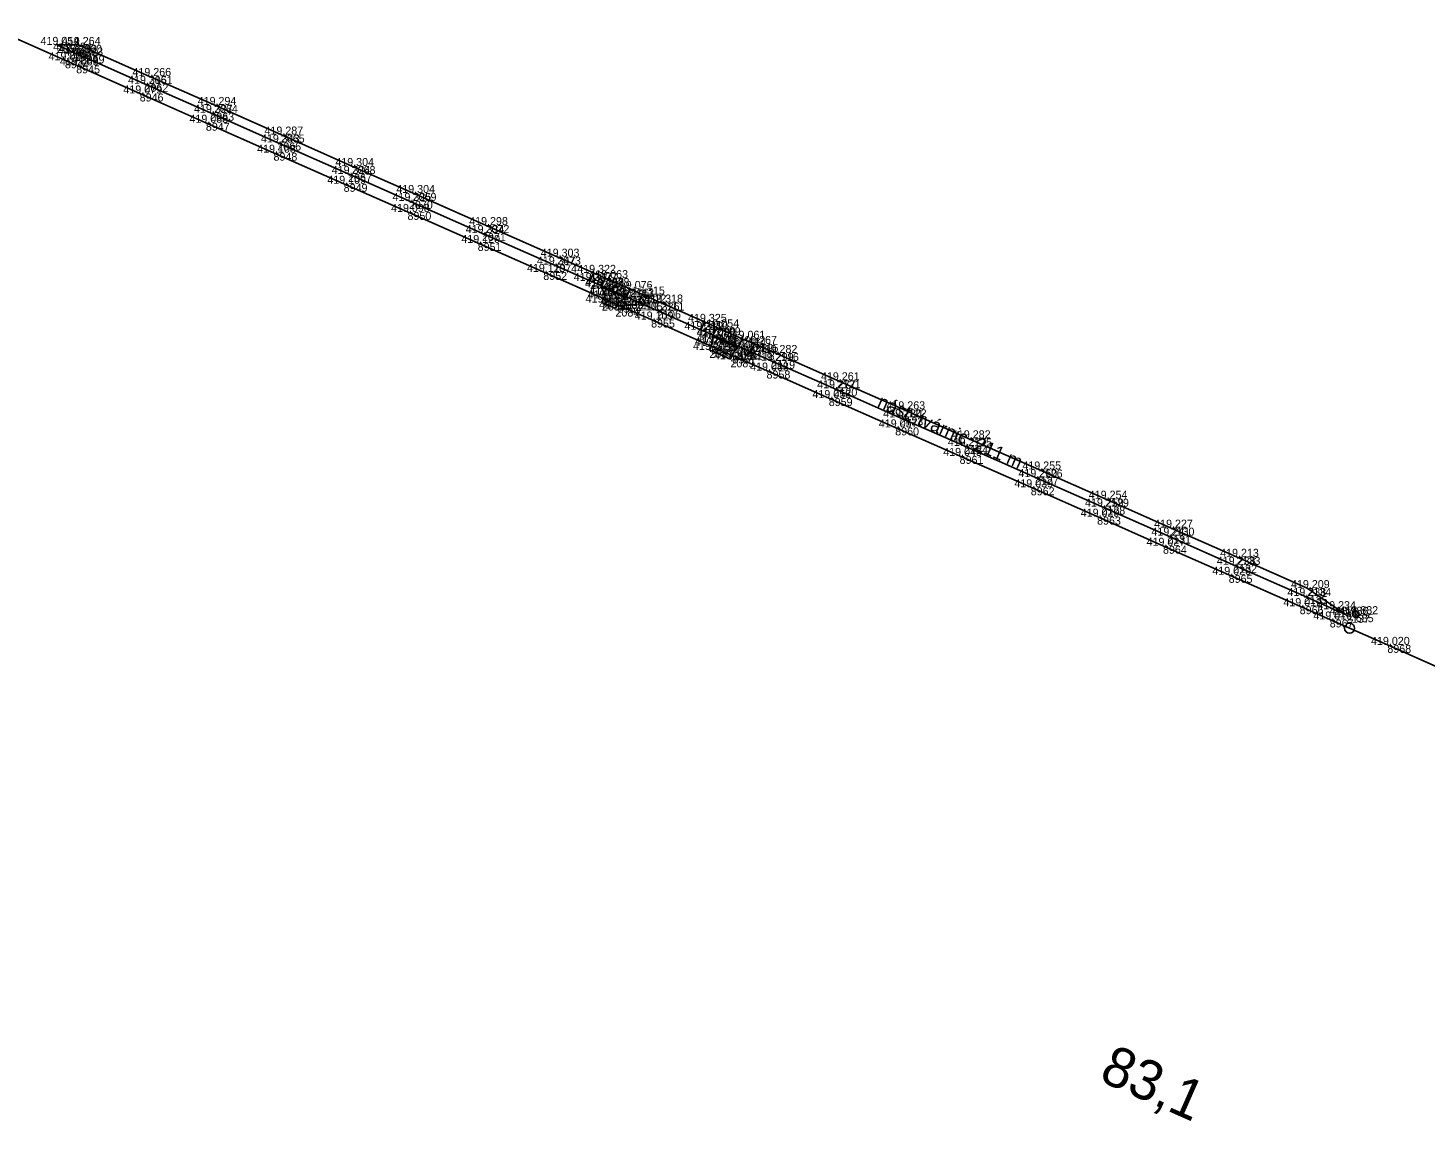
# Model space of a CAD drawing. Extents: x -599511 to -595511, y -1067427 to -1062061.
# Drawn here: x -598996.7 to -598787.3, y -1062489.7 to -1062325.8 of the extents above; entities that cross this region are included whole.
import ezdxf

# ---------------------------------------------------------------- set-up
doc = ezdxf.new("R2010")
doc.units = 0
for name, color, linetype in [('Vrstva 1', 7, 'Continuous'), ('Vrstva 14', 7, 'Continuous'), ('Vrstva 4', 7, 'Continuous'), ('Vrstva 60', 7, 'Continuous'), ('Vrstva 61', 7, 'Continuous'), ('Vrstva 7', 7, 'Continuous')]:
    doc.layers.add(name, color=color, linetype=linetype)

msp = doc.modelspace()

# ---------------------------------------------------------------- linework, layer by layer
at = {"layer": 'Vrstva 1'}
msp.add_lwpolyline([(-599002.16, -1062325.8), (-598991.2, -1062330.65), (-598989.51, -1062331.4), (-598979.99, -1062335.62), (-598970.07, -1062340.01), (-598959.93, -1062344.5), (-598949.41, -1062349.16), (-598939.84, -1062353.38), (-598929.32, -1062358.03), (-598919.48, -1062362.38), (-598910.47, -1062366.35), (-598908.33, -1062367.29), (-598903.32, -1062369.51), (-598894.33, -1062373.48), (-598891.15, -1062374.89), (-598886.01, -1062377.16), (-598876.68, -1062381.28), (-598866.72, -1062385.68), (-598857.06, -1062389.95), (-598846.4, -1062394.66), (-598836.45, -1062399.06), (-598826.57, -1062403.42), (-598816.72, -1062407.78), (-598806.07, -1062412.48), (-598801.57, -1062414.47), (-598792.93, -1062418.28), (-598782.71, -1062422.8)], dxfattribs=at)
at = {"layer": 'Vrstva 14'}
for p, q in [((-598912.46, -1062363.71), (-598911.94, -1062362.51)), ((-598910.72, -1062364.45), (-598910.13, -1062363.31)), ((-598907, -1062366.09), (-598906.45, -1062364.93)), ((-598905.14, -1062366.95), (-598904.6, -1062365.76)), ((-598895.86, -1062371.05), (-598895.33, -1062369.86)), ((-598893.99, -1062371.86), (-598893.46, -1062370.68)), ((-598890.2, -1062373.54), (-598889.64, -1062372.39)), ((-598888.36, -1062374.35), (-598887.8, -1062373.17))]:
    msp.add_line(p, q, dxfattribs=at)
msp.add_lwpolyline([(-598799.13, -1062413.77), (-598800.99, -1062412.93), (-598805.46, -1062410.95), (-598816.05, -1062406.27), (-598825.94, -1062401.89), (-598835.8, -1062397.54), (-598845.79, -1062393.13), (-598856.38, -1062388.46), (-598866.08, -1062384.18), (-598875.97, -1062379.82), (-598885.3, -1062375.7), (-598888.36, -1062374.35), (-598890.2, -1062373.54), (-598893.99, -1062371.86), (-598895.86, -1062371.05), (-598902.41, -1062368.15), (-598905.14, -1062366.95), (-598907, -1062366.09), (-598910.72, -1062364.45), (-598912.46, -1062363.71), (-598917.99, -1062361.27), (-598928.67, -1062356.55), (-598939.62, -1062351.72), (-598948.75, -1062347.68), (-598959.36, -1062342.97), (-598969.4, -1062338.51), (-598979.27, -1062334.17), (-598988.84, -1062329.93), (-598989.76, -1062329.53), (-598990.51, -1062329.2), (-598992.41, -1062328.34), (-598989.21, -1062328.35), (-598978.63, -1062333.01), (-598968.85, -1062337.34), (-598958.83, -1062341.78), (-598948.21, -1062346.5), (-598939.07, -1062350.54), (-598928.14, -1062355.35), (-598917.41, -1062360.09), (-598911.94, -1062362.51), (-598910.13, -1062363.31), (-598906.45, -1062364.93), (-598904.6, -1062365.76), (-598901.89, -1062366.96), (-598895.33, -1062369.86), (-598893.46, -1062370.68), (-598889.64, -1062372.39), (-598887.8, -1062373.17), (-598884.74, -1062374.52), (-598875.49, -1062378.62), (-598865.58, -1062382.97), (-598855.78, -1062387.32), (-598845.19, -1062391.99), (-598835.25, -1062396.37), (-598825.43, -1062400.71), (-598815.54, -1062405.08), (-598804.93, -1062409.77)], close=True, dxfattribs=at)
at = {"layer": 'Vrstva 4'}
for points in [[(-598910.78, -1062364.68), (-598910.2, -1062365.77), (-598910.69, -1062366.96), (-598908.66, -1062367.86), (-598908.05, -1062366.74), (-598907.11, -1062366.28)], [(-598894.04, -1062372.07), (-598890.35, -1062373.71), (-598890.88, -1062374.33), (-598891.42, -1062375.47), (-598894.58, -1062374.06), (-598894.06, -1062372.91)]]:
    msp.add_lwpolyline(points, close=True, dxfattribs=at)
at = {"layer": 'Vrstva 60'}
for p, q in [((-598992.41, -1062328.34), (-598992.41, -1062328.34)), ((-598990.51, -1062329.2), (-598990.51, -1062329.2)), ((-598989.76, -1062329.53), (-598989.76, -1062329.53)), ((-598989.21, -1062328.35), (-598989.21, -1062328.35)), ((-598988.84, -1062329.93), (-598988.84, -1062329.93)), ((-598991.2, -1062330.65), (-598991.2, -1062330.65)), ((-598989.51, -1062331.4), (-598989.51, -1062331.4)), ((-598979.27, -1062334.17), (-598979.27, -1062334.17)), ((-598978.63, -1062333.01), (-598978.63, -1062333.01)), ((-598979.99, -1062335.62), (-598979.99, -1062335.62)), ((-598968.85, -1062337.34), (-598968.85, -1062337.34)), ((-598970.07, -1062340.01), (-598970.07, -1062340.01)), ((-598969.4, -1062338.51), (-598969.4, -1062338.51)), ((-598958.83, -1062341.78), (-598958.83, -1062341.78)), ((-598959.93, -1062344.5), (-598959.93, -1062344.5)), ((-598959.36, -1062342.97), (-598959.36, -1062342.97)), ((-598948.21, -1062346.5), (-598948.21, -1062346.5)), ((-598948.75, -1062347.68), (-598948.75, -1062347.68)), ((-598949.41, -1062349.16), (-598949.41, -1062349.16)), ((-598939.07, -1062350.54), (-598939.07, -1062350.54)), ((-598939.62, -1062351.72), (-598939.62, -1062351.72)), ((-598939.84, -1062353.38), (-598939.84, -1062353.38)), ((-598928.67, -1062356.55), (-598928.67, -1062356.55)), ((-598928.14, -1062355.35), (-598928.14, -1062355.35)), ((-598929.32, -1062358.03), (-598929.32, -1062358.03)), ((-598917.99, -1062361.27), (-598917.99, -1062361.27)), ((-598917.41, -1062360.09), (-598917.41, -1062360.09)), ((-598919.48, -1062362.38), (-598919.48, -1062362.38)), ((-598911.94, -1062362.51), (-598911.94, -1062362.51)), ((-598910.13, -1062363.31), (-598910.13, -1062363.31)), ((-598912.46, -1062363.71), (-598912.46, -1062363.71)), ((-598910.78, -1062364.68), (-598910.78, -1062364.68)), ((-598910.72, -1062364.45), (-598910.72, -1062364.45)), ((-598906.45, -1062364.93), (-598906.45, -1062364.93)), ((-598910.69, -1062366.96), (-598910.69, -1062366.96)), ((-598910.47, -1062366.35), (-598910.47, -1062366.35)), ((-598910.2, -1062365.77), (-598910.2, -1062365.77)), ((-598908.33, -1062367.29), (-598908.33, -1062367.29)), ((-598908.05, -1062366.74), (-598908.05, -1062366.74)), ((-598907.11, -1062366.28), (-598907.11, -1062366.28)), ((-598907, -1062366.09), (-598907, -1062366.09)), ((-598905.14, -1062366.95), (-598905.14, -1062366.95)), ((-598904.6, -1062365.76), (-598904.6, -1062365.76)), ((-598901.89, -1062366.96), (-598901.89, -1062366.96)), ((-598908.66, -1062367.86), (-598908.66, -1062367.86)), ((-598903.32, -1062369.51), (-598903.32, -1062369.51)), ((-598902.41, -1062368.15), (-598902.41, -1062368.15)), ((-598895.86, -1062371.05), (-598895.86, -1062371.05)), ((-598895.33, -1062369.86), (-598895.33, -1062369.86)), ((-598893.99, -1062371.86), (-598893.99, -1062371.86)), ((-598893.46, -1062370.68), (-598893.46, -1062370.68)), ((-598894.33, -1062373.48), (-598894.33, -1062373.48)), ((-598894.06, -1062372.91), (-598894.06, -1062372.91)), ((-598894.04, -1062372.07), (-598894.04, -1062372.07)), ((-598890.35, -1062373.71), (-598890.35, -1062373.71)), ((-598890.2, -1062373.54), (-598890.2, -1062373.54)), ((-598889.64, -1062372.39), (-598889.64, -1062372.39)), ((-598887.8, -1062373.17), (-598887.8, -1062373.17)), ((-598894.58, -1062374.06), (-598894.58, -1062374.06)), ((-598891.42, -1062375.47), (-598891.42, -1062375.47)), ((-598891.15, -1062374.89), (-598891.15, -1062374.89)), ((-598890.88, -1062374.33), (-598890.88, -1062374.33)), ((-598888.36, -1062374.35), (-598888.36, -1062374.35)), ((-598885.3, -1062375.7), (-598885.3, -1062375.7)), ((-598884.74, -1062374.52), (-598884.74, -1062374.52)), ((-598886.01, -1062377.16), (-598886.01, -1062377.16)), ((-598875.97, -1062379.82), (-598875.97, -1062379.82)), ((-598875.49, -1062378.62), (-598875.49, -1062378.62)), ((-598876.68, -1062381.28), (-598876.68, -1062381.28)), ((-598866.08, -1062384.18), (-598866.08, -1062384.18)), ((-598865.58, -1062382.97), (-598865.58, -1062382.97)), ((-598866.72, -1062385.68), (-598866.72, -1062385.68)), ((-598856.38, -1062388.46), (-598856.38, -1062388.46)), ((-598855.78, -1062387.32), (-598855.78, -1062387.32)), ((-598857.06, -1062389.95), (-598857.06, -1062389.95)), ((-598845.19, -1062391.99), (-598845.19, -1062391.99)), ((-598846.4, -1062394.66), (-598846.4, -1062394.66)), ((-598845.79, -1062393.13), (-598845.79, -1062393.13)), ((-598835.25, -1062396.37), (-598835.25, -1062396.37)), ((-598836.45, -1062399.06), (-598836.45, -1062399.06)), ((-598835.8, -1062397.54), (-598835.8, -1062397.54)), ((-598825.43, -1062400.71), (-598825.43, -1062400.71)), ((-598825.94, -1062401.89), (-598825.94, -1062401.89)), ((-598826.57, -1062403.42), (-598826.57, -1062403.42)), ((-598815.54, -1062405.08), (-598815.54, -1062405.08)), ((-598816.05, -1062406.27), (-598816.05, -1062406.27)), ((-598816.72, -1062407.78), (-598816.72, -1062407.78)), ((-598805.46, -1062410.95), (-598805.46, -1062410.95)), ((-598804.93, -1062409.77), (-598804.93, -1062409.77)), ((-598806.07, -1062412.48), (-598806.07, -1062412.48)), ((-598800.99, -1062412.93), (-598800.99, -1062412.93)), ((-598799.13, -1062413.77), (-598799.13, -1062413.77)), ((-598797.66, -1062413.68), (-598797.66, -1062413.68)), ((-598801.57, -1062414.47), (-598801.57, -1062414.47)), ((-598792.93, -1062418.28), (-598792.93, -1062418.28))]:
    msp.add_line(p, q, dxfattribs=at)
at = {"layer": 'Vrstva 7'}
msp.add_line((-598797.71, -1062413.65), (-598797.62, -1062413.7), dxfattribs=at)
for centre, radius in [((-598797.66, -1062413.68), 0.5), ((-598798.59, -1062415.79), 0.75)]:
    msp.add_circle(centre, radius, dxfattribs=at)

# ---------------------------------------------------------------- texts
at = {"layer": 'Vrstva 14'}
msp.add_text('nást. tvárnic. 211 m', height=2, rotation=336.2761, dxfattribs=at).set_placement((-598869.53, -1062382.52))
at = {"layer": 'Vrstva 60'}
for s, p in [('2056', (-598992.41, -1062329.54)), ('2057', (-598990.51, -1062330.4)), ('2058', (-598989.76, -1062330.73)), ('2060', (-598989.21, -1062329.55)), ('2059', (-598988.84, -1062331.13)), ('8944', (-598991.2, -1062331.85)), ('8945', (-598989.51, -1062332.6)), ('2062', (-598979.27, -1062335.37)), ('2061', (-598978.63, -1062334.21)), ('8946', (-598979.99, -1062336.82)), ('2064', (-598968.85, -1062338.54)), ('8947', (-598970.07, -1062341.21)), ('2063', (-598969.4, -1062339.71)), ('2065', (-598958.83, -1062342.98)), ('8948', (-598959.93, -1062345.7)), ('2066', (-598959.36, -1062344.17)), ('2068', (-598948.21, -1062347.7)), ('2067', (-598948.75, -1062348.88)), ('8949', (-598949.41, -1062350.36)), ('2069', (-598939.07, -1062351.74)), ('2070', (-598939.62, -1062352.92)), ('8950', (-598939.84, -1062354.58)), ('2071', (-598928.67, -1062357.75)), ('2072', (-598928.14, -1062356.55)), ('8951', (-598929.32, -1062359.23)), ('2074', (-598917.99, -1062362.47)), ('2073', (-598917.41, -1062361.29)), ('8952', (-598919.48, -1062363.58)), ('2077', (-598911.94, -1062363.71)), ('2078', (-598910.13, -1062364.51)), ('2075', (-598912.46, -1062364.91)), ('2079', (-598910.78, -1062365.88)), ('2076', (-598910.72, -1062365.65)), ('2113', (-598906.45, -1062366.13)), ('2083', (-598910.69, -1062368.16)), ('8953', (-598910.47, -1062367.55)), ('2086', (-598910.2, -1062366.97)), ('8954', (-598908.33, -1062368.49)), ('2085', (-598908.05, -1062367.94)), ('2080', (-598907.11, -1062367.48)), ('2103', (-598907, -1062367.29)), ('2105', (-598905.14, -1062368.15)), ('2112', (-598904.6, -1062366.96)), ('2111', (-598901.89, -1062368.16)), ('2084', (-598908.66, -1062369.06)), ('8955', (-598903.32, -1062370.71)), ('2106', (-598902.41, -1062369.34)), ('2110', (-598895.33, -1062371.06)), ('2107', (-598895.86, -1062372.25)), ('2108', (-598893.99, -1062373.06)), ('2109', (-598893.46, -1062371.88)), ('8956', (-598894.33, -1062374.68)), ('2093', (-598894.06, -1062374.11)), ('2094', (-598894.04, -1062373.27)), ('2095', (-598890.35, -1062374.91)), ('2117', (-598890.2, -1062374.74)), ('2114', (-598889.64, -1062373.59)), ('2115', (-598887.8, -1062374.37)), ('2087', (-598894.58, -1062375.26)), ('2089', (-598891.42, -1062376.67)), ('8957', (-598891.15, -1062376.09)), ('2091', (-598890.88, -1062375.53)), ('2118', (-598888.36, -1062375.55)), ('2119', (-598885.3, -1062376.9)), ('2116', (-598884.74, -1062375.72)), ('8958', (-598886.01, -1062378.36)), ('2120', (-598875.97, -1062381.02)), ('2121', (-598875.49, -1062379.82)), ('8959', (-598876.68, -1062382.48)), ('2123', (-598866.08, -1062385.38)), ('2122', (-598865.58, -1062384.17)), ('8960', (-598866.72, -1062386.88)), ('2124', (-598856.38, -1062389.66)), ('2125', (-598855.78, -1062388.52)), ('8961', (-598857.06, -1062391.15)), ('2126', (-598845.19, -1062393.19)), ('8962', (-598846.4, -1062395.86)), ('2127', (-598845.79, -1062394.33)), ('2129', (-598835.25, -1062397.57)), ('8963', (-598836.45, -1062400.26)), ('2128', (-598835.8, -1062398.74)), ('2130', (-598825.43, -1062401.91)), ('2131', (-598825.94, -1062403.09)), ('8964', (-598826.57, -1062404.62)), ('2133', (-598815.54, -1062406.28)), ('2132', (-598816.05, -1062407.47)), ('8965', (-598816.72, -1062408.98)), ('2135', (-598805.46, -1062412.15)), ('2134', (-598804.93, -1062410.97)), ('8966', (-598806.07, -1062413.68)), ('2136', (-598800.99, -1062414.13)), ('2137', (-598799.13, -1062414.97)), ('685', (-598797.66, -1062414.88)), ('8967', (-598801.57, -1062415.67)), ('8968', (-598792.93, -1062419.48))]:
    msp.add_text(s, height=1.2, dxfattribs=at).set_placement(p)
at = {"layer": 'Vrstva 61'}
for s, p in [('419.054', (-598994.86, -1062328.34)), ('419.264', (-598991.66, -1062328.35)), ('419.067', (-598993.66, -1062330.65)), ('419.324', (-598992.96, -1062329.2)), ('419.322', (-598992.21, -1062329.53)), ('419.323', (-598991.29, -1062329.93)), ('419.063', (-598991.96, -1062331.4)), ('419.266', (-598981.08, -1062333.01)), ('419.315', (-598981.73, -1062334.17)), ('419.079', (-598982.44, -1062335.62)), ('419.294', (-598971.3, -1062337.34)), ('419.327', (-598971.85, -1062338.51)), ('419.088', (-598972.53, -1062340.01)), ('419.343', (-598961.81, -1062342.97)), ('419.287', (-598961.28, -1062341.78)), ('419.108', (-598962.38, -1062344.5)), ('419.324', (-598951.2, -1062347.68)), ('419.304', (-598950.66, -1062346.5)), ('419.109', (-598951.86, -1062349.16)), ('419.325', (-598942.08, -1062351.72)), ('419.304', (-598941.52, -1062350.54)), ('419.098', (-598942.3, -1062353.38)), ('419.298', (-598930.59, -1062355.35)), ('419.120', (-598931.77, -1062358.03)), ('419.334', (-598931.12, -1062356.55)), ('419.303', (-598919.86, -1062360.09)), ('419.119', (-598921.93, -1062362.38)), ('419.347', (-598920.44, -1062361.27)), ('419.322', (-598914.39, -1062362.51)), ('419.347', (-598914.91, -1062363.71)), ('419.063', (-598913.23, -1062364.68)), ('419.078', (-598913.17, -1062364.45)), ('419.063', (-598912.58, -1062363.31)), ('419.121', (-598912.83, -1062366.35)), ('419.131', (-598912.56, -1062365.77)), ('419.133', (-598910.5, -1062366.74)), ('419.091', (-598909.46, -1062366.28)), ('419.106', (-598909.46, -1062366.09)), ('419.076', (-598908.9, -1062364.93)), ('419.315', (-598907.06, -1062365.76)), ('419.136', (-598913.14, -1062366.96)), ('419.139', (-598911.11, -1062367.86)), ('419.118', (-598910.79, -1062367.29)), ('419.332', (-598907.59, -1062366.95)), ('419.326', (-598904.86, -1062368.15)), ('419.318', (-598904.34, -1062366.96)), ('419.109', (-598905.77, -1062369.51)), ('419.319', (-598898.32, -1062371.05)), ('419.325', (-598897.78, -1062369.86)), ('419.054', (-598895.91, -1062370.68)), ('419.103', (-598896.51, -1062372.91)), ('419.086', (-598896.49, -1062372.07)), ('419.099', (-598896.44, -1062371.86)), ('419.061', (-598891.99, -1062372.39)), ('419.108', (-598897.03, -1062374.06)), ('419.095', (-598896.79, -1062373.48)), ('419.094', (-598893.6, -1062374.89)), ('419.092', (-598893.33, -1062374.33)), ('419.073', (-598892.8, -1062373.71)), ('419.056', (-598892.66, -1062373.54)), ('419.289', (-598890.81, -1062374.35)), ('419.267', (-598890.25, -1062373.17)), ('419.282', (-598887.19, -1062374.52)), ('419.108', (-598893.88, -1062375.47)), ('419.088', (-598888.47, -1062377.16)), ('419.299', (-598887.76, -1062375.7)), ('419.261', (-598877.85, -1062378.62)), ('419.058', (-598879.13, -1062381.28)), ('419.277', (-598878.42, -1062379.82)), ('419.263', (-598868.03, -1062382.97)), ('419.057', (-598869.17, -1062385.68)), ('419.280', (-598868.53, -1062384.18)), ('419.282', (-598858.22, -1062387.32)), ('419.277', (-598858.83, -1062388.46)), ('419.045', (-598859.52, -1062389.95)), ('419.255', (-598847.65, -1062391.99)), ('419.260', (-598848.24, -1062393.13)), ('419.039', (-598848.85, -1062394.66)), ('419.259', (-598838.26, -1062397.54)), ('419.254', (-598837.7, -1062396.37)), ('419.029', (-598838.9, -1062399.06)), ('419.241', (-598828.3, -1062401.89)), ('419.227', (-598827.89, -1062400.71)), ('419.027', (-598829.03, -1062403.42)), ('419.238', (-598818.5, -1062406.27)), ('419.213', (-598818, -1062405.08)), ('419.020', (-598819.17, -1062407.78)), ('419.209', (-598807.38, -1062409.77)), ('419.012', (-598808.52, -1062412.48)), ('419.238', (-598807.91, -1062410.95)), ('419.234', (-598803.44, -1062412.93)), ('419.016', (-598804.02, -1062414.47)), ('418.986', (-598801.58, -1062413.77)), ('418.882', (-598800.11, -1062413.68)), ('419.020', (-598795.38, -1062418.28))]:
    msp.add_text(s, height=1.2, dxfattribs=at).set_placement(p)
at = {"layer": 'Vrstva 7'}
msp.add_text('83,1', height=6, rotation=336.2094, dxfattribs=at).set_placement((-598836.35, -1062483.52))

doc.saveas('drawing.dxf')
